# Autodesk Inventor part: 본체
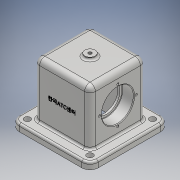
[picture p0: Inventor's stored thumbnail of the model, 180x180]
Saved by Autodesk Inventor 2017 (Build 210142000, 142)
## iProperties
Part Number: 본체
Material: 알루미늄 6061
Document SubType Name: Modeling
Designer: MRC
Density: 2.7 g/cm^3
Appearance: 알루미늄 - 평지
Mass: 1059.83 g
Surface Area: 721.846 cm^2
Volume: 392.53 cm^3
Author: MRC
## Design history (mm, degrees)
sketch "스케치2"
  geometry: L1 (-58, 58)-(58, 58); L2 (58, 58)-(58, -58); L3 (58, -58)-(-58, -58); L4 (-58, -58)-(-58, 58); L5 (-58, 58)-(58, -58); L6 (58, 58)-(-58, -58); 1 further point
  constraints: 12 end point, 2 midpoint, 2 parallel, 1 horizontal, 1 perpendicular
  dimensions: "d2" = 116 distance of L2.end L3.end; "d3" = 116 distance of L1.end L2.end
extrude "돌출1" new body sketch "스케치2" distance "d4" = 10; taper "d5" = 0 deg
sketch "스케치3"
  geometry: L1 (-41, 41)-(41, 41); L2 (41, 41)-(41, -41); L3 (41, -41)-(-41, -41); L4 (-41, -41)-(-41, 41); L5 (-41, 41)-(41, -41); L6 (41, 41)-(-41, -41); 1 further point
  constraints: 12 end point, 2 midpoint, 2 parallel, 1 horizontal, 1 perpendicular
  dimensions: "d6" = 82 distance of L1.start L1.end; "d7" = 82 distance of L1.end L2.end
extrude "돌출2" join sketch "스케치3" distance "d8" = 80; taper "d9" = 0 deg
fillet "모깎기1" dims "d10" = 12
sketch "스케치4"
  geometry: L1 (10, 87)-(10, -5) reference; 4 further points
  constraints: 2 midpoint, 1 horizontal alignment
  dimensions: "d13" = 48 distance of point (10, 41) point (-38, 41)
hole "구멍1" sketch "스케치4" at (-38, 41) diameter "d14" = 40; stored, may be unused: countersink angle "d18" = 90 deg, drill point angle "d20" = 118 deg; dims "d15" = 6, "d16" = 47, "d17" = 17, "d19" = 8
sketch "스케치5"
  geometry: L1 (10, 87)-(10, -5) reference; C1 r 20 at (-38, 41) reference; 3 further points
  constraints: 1 horizontal alignment, 1 midpoint
  dimensions: "d21" = 27 distance of C1.centre point (-65, 41)
hole "구멍2" sketch "스케치5" at (-65, 41) diameter "d22" = 3.242; stored, may be unused: countersink angle "d26" = 90 deg, drill point angle "d28" = 118 deg; dims "d23" = 8, "d24" = 47, "d25" = 17, "d27" = 10
chamfer "모따기1" distance "d32" = 1; stored, may be unused: second distance "d33" = 2, angle "d34" = 45 deg
chamfer "모따기2" distance "d35" = 1; stored, may be unused: second distance "d36" = 2, angle "d37" = 45 deg
sketch "스케치6"
  geometry: L1 (-21, 30)-(21, 30); L2 (21, 30)-(21, -30); L3 (21, -30)-(-21, -30); L4 (-21, -30)-(-21, 30); L5 (-21, 30)-(21, -30); L6 (21, 30)-(-21, -30); 1 further point
  constraints: 12 end point, 2 midpoint, 2 parallel, 1 horizontal, 1 perpendicular
  dimensions: "d38" = 42 distance of L1.start L1.end; "d39" = 60 distance of L1.end L2.end
extrude "돌출3" cut sketch "스케치6" distance "d40" = 80; taper "d41" = 0 deg
sketch "스케치7"
  geometry: C1 r 7.5 at (0, 0); 1 further point
  constraints: 1 centre point, 1 coincident
  dimensions: "d42" = 15 diameter of C1
extrude "돌출4" join sketch "스케치7" distance "d43" = 4; taper "d44" = 0 deg
sketch "스케치8"
  geometry: C1 r 7.5 at (0, 0) reference; 2 further points
  constraints: 1 coincident
hole "구멍3" sketch "스케치8" at (0, 0) diameter "d45" = 4.917; stored, may be unused: countersink angle "d49" = 90 deg, drill point angle "d51" = 118 deg; dims "d46" = 12, "d47" = 47, "d48" = 17, "d50" = 17.1
fillet "모깎기2" dims "d52" = 3
fillet "모깎기3" dims "d53" = 8
fillet "모깎기4" dims "d54" = 8
fillet "모깎기5" dims "d55" = 3
fillet "모깎기6" dims "d56" = 3
fillet "모깎기7" dims "d57" = 3
sketch "스케치9"
  geometry: A1 r 9 centre (46, 46) between (55, 46) and (46, 55) reference; 2 further points
  constraints: 1 coincident
hole "구멍4" sketch "스케치9" at (46, 46) diameter "d58" = 9; stored, may be unused: countersink angle "d62" = 90 deg, drill point angle "d64" = 118 deg; dims "d59" = 6, "d60" = 4, "d61" = 2, "d63" = 8
fillet "모깎기8" dims "d65" = 0.6
sketch "스케치10"
  geometry: L1 (79, -82)-(-13, -82) reference; 3 further points
  constraints: 1 midpoint, 1 vertical alignment, 1 other
  dimensions: "d66" = 48 distance from line of L1 point (33, -34)
feature "엠보싱1" sketch "스케치10" dims "d2" = 116, "d3" = 116, "d67" = 0.5, "d68" = 0
node "솔리드1"
pattern_circular "원형 패턴1" dims angle "d30" = 360 deg
mirror "미러1"
mirror "미러2"
mirror "미러3"
